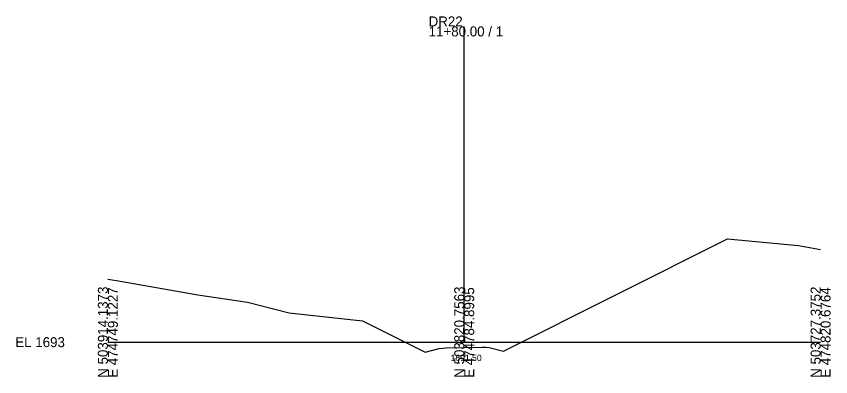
# Model space of a CAD drawing. Extents: x -26 to 1203, y -10 to 9633.
# Drawn here: x -25.7 to 202.8, y 4490.3 to 4591.5 of the extents above; entities that cross this region are included whole.
import ezdxf

# ---------------------------------------------------------------- set-up
doc = ezdxf.new("R2010")
doc.units = 0
for name, color, linetype in [('Exist Cross Section Cell', 7, 'Continuous'), ('Exist XS Center Line Elevation Label', 7, 'Continuous'), ('Exist XS Ground Line', 7, 'Continuous'), ('Scratch_Level_5', 7, 'Continuous')]:
    doc.layers.add(name, color=color, linetype=linetype)

msp = doc.modelspace()

# ---------------------------------------------------------------- linework, layer by layer
at = {"layer": 'Exist Cross Section Cell'}
for p, q in [((100, 4500), (100, 4588.61)), ((0, 4500), (100, 4500)), ((100, 4500), (200, 4500))]:
    msp.add_line(p, q, dxfattribs=at)
at = {"layer": 'Exist XS Ground Line'}
msp.add_lwpolyline([(0, 4517.72), (2.45, 4517.33), (25.25, 4513.25), (39.14, 4511.19), (50.87, 4508.21), (71.41, 4506.03), (89, 4497.24), (93, 4498.24), (93.98, 4498.31), (95, 4498.4), (100, 4498.5), (105, 4498.6), (106.02, 4498.56), (107, 4498.52), (111, 4497.52), (173.91, 4528.97), (192.75, 4527.23), (193.78, 4527.14), (195.89, 4526.73), (200, 4526.03)], dxfattribs=at)
at = {"layer": 'Scratch_Level_5'}
msp.add_lwpolyline([(0, 4517.72), (2.45, 4517.33), (25.25, 4513.25), (39.14, 4511.19), (50.87, 4508.21), (71.41, 4506.03), (89, 4497.24), (93, 4498.24), (93.98, 4498.31), (95, 4498.4), (100, 4498.5), (105, 4498.6), (106.02, 4498.56), (107, 4498.52), (111, 4497.52), (173.91, 4528.97), (192.75, 4527.23), (193.78, 4527.14), (195.89, 4526.73), (200, 4526.03)], dxfattribs=at)

# ---------------------------------------------------------------- texts
at = {"layer": 'Exist Cross Section Cell'}
for s, p in [('DR22', (90, 4588.61)), ('11+80.00 / 1', (90, 4585.81)), ('EL 1693', (-26, 4498.6))]:
    msp.add_text(s, height=2.8, dxfattribs=at).set_placement(p)
for s, p in [('N 503914.1373', (0, 4490)), ('E 474749.1227', (2.8, 4490)), ('N 503820.7563', (100, 4490)), ('E 474784.8995', (102.8, 4490)), ('N 503727.3752', (200, 4490)), ('E 474820.6764', (202.8, 4490))]:
    msp.add_text(s, height=2.8, rotation=90, dxfattribs=at).set_placement(p)
at = {"layer": 'Exist XS Center Line Elevation Label'}
msp.add_text('1691.50', height=1.8, dxfattribs=at).set_placement((96.19, 4494.7))

doc.saveas('drawing.dxf')
